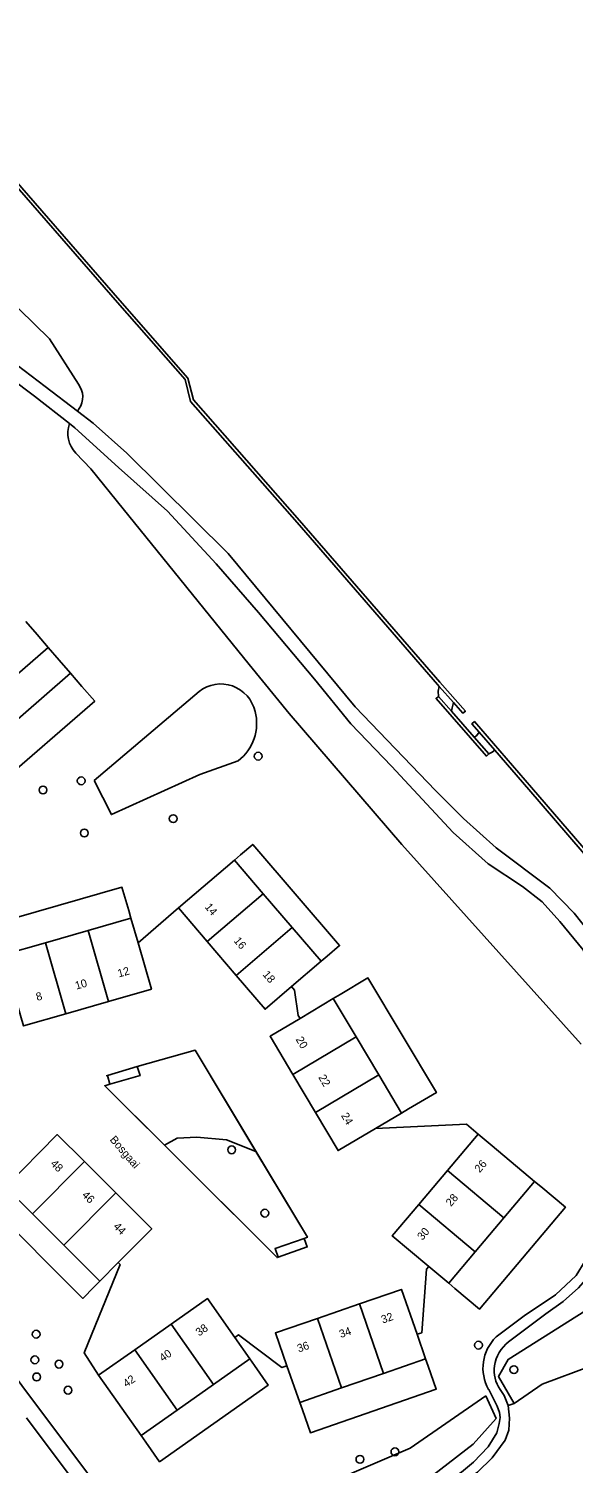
# Model space of a CAD drawing. Extents: x 156664 to 157568, y 383571 to 384421.
# Drawn here: x 156972.4 to 157040.6, y 384130.7 to 384310 of the extents above; entities that cross this region are included whole.
import ezdxf

# ---------------------------------------------------------------- set-up
doc = ezdxf.new("R2010")
doc.units = 0
for name, color, linetype in [('IMGEO_Boom', 7, 'Continuous'), ('IMGEO_Grasland_overig', 7, 'Continuous'), ('IMGEO_Greppel_droge_sloot', 7, 'Continuous'), ('IMGEO_Groenvoorziening', 7, 'Continuous'), ('IMGEO_Hek', 7, 'Continuous'), ('IMGEO_Houtwal', 7, 'Continuous'), ('IMGEO_Kademuur', 7, 'Continuous'), ('IMGEO_Loofbos', 7, 'Continuous'), ('IMGEO_Meer_plas_ven_vijver', 7, 'Continuous'), ('IMGEO_Muur', 7, 'Continuous'), ('IMGEO_Openbare_ruimte_label', 7, 'Continuous'), ('IMGEO_Pand', 7, 'Continuous'), ('IMGEO_Pand_nummerreeks', 7, 'Continuous'), ('IMGEO_Voetpad_halfverhard', 7, 'Continuous'), ('IMGEO_Voetpad_open', 7, 'Continuous'), ('IMGEO_Waterloop', 7, 'Continuous')]:
    doc.layers.add(name, color=color, linetype=linetype)

msp = doc.modelspace()

# ---------------------------------------------------------------- linework, layer by layer
at = {"layer": 'IMGEO_Boom'}
for centre in [(157001.12, 384219.07), (156978.98, 384215.99), (156974.2, 384214.85), (156990.49, 384211.27), (156979.37, 384209.47), (156997.8, 384169.88), (157001.96, 384161.96), (156973.34, 384146.83), (157028.68, 384145.46), (156973.18, 384143.62), (156976.2, 384143.09), (157033.11, 384142.4), (156973.41, 384141.49), (156977.33, 384139.83), (157018.23, 384132.13), (157013.85, 384131.19)]:
    msp.add_circle(centre, 0.489, dxfattribs=at)
at = {"layer": 'IMGEO_Grasland_overig'}
for points in [[(156986, 384180.27), (156993.22, 384182.35), (157000.84, 384169.66)], [(156982.58, 384178.07), (156982.26, 384179.17), (156986, 384180.27)], [(156986, 384180.27), (156986.35, 384179.16), (156982.58, 384178.07)], [(156989.38, 384170.45), (156981.92, 384177.88), (156982.58, 384178.07)], [(156989.38, 384170.45), (156990.98, 384171.33), (156993.45, 384171.47), (156997.15, 384171.11), (157000.84, 384169.66)], [(157003.64, 384156.45), (157003.49, 384156.4), (156989.38, 384170.45)], [(157000.84, 384169.66), (157007.28, 384158.95), (157006.89, 384158.81)], [(157003.64, 384156.45), (157003.24, 384157.52), (157006.89, 384158.81)], [(157006.89, 384158.81), (157007.25, 384157.74), (157003.64, 384156.45)]]:
    msp.add_lwpolyline(points, dxfattribs=at)
at = {"layer": 'IMGEO_Greppel_droge_sloot'}
for points in [[(157073.18, 384136.62), (157070.19, 384141.01), (157064.98, 384144.51), (157061.93, 384147.4), (157059.42, 384149.63), (157057.67, 384151.81), (157054.48, 384157.38), (157052.61, 384158.91), (157049.33, 384158.7), (157048.02, 384157.03), (157047.08, 384153.92), (157045.3, 384151.79), (157032.38, 384143.68), (157031.2, 384141.56), (157033.15, 384138.17)], [(157033.15, 384138.17), (157036.64, 384140.57), (157042.69, 384142.82), (157047.48, 384142.77), (157050.7, 384143.97), (157052.89, 384145.51), (157055.6, 384145.94), (157058.37, 384145.32), (157062.52, 384143.02), (157073.18, 384136.62)], [(157029.6, 384139.14), (157030.88, 384136.29), (157028.03, 384133.07), (157020.85, 384127.54), (157011.12, 384122.68), (157001.81, 384121.29), (156998.76, 384122.64), (157003.7, 384126.69), (157011.98, 384129.07), (157020.14, 384132.57), (157029.6, 384139.14)]]:
    msp.add_lwpolyline(points, dxfattribs=at)
at = {"layer": 'IMGEO_Groenvoorziening'}
for points in [[(156998.14, 384206.08), (156998.9, 384206.73), (157000.44, 384208.05), (157011.3, 384195.41), (157009.75, 384194.09), (157008.99, 384193.45)], [(156969.2, 384194.23), (156968.92, 384195.19), (156968.07, 384198.1), (156984.07, 384202.7), (156984.92, 384199.79), (156985.2, 384198.82)], [(156986.09, 384195.75), (156991.14, 384200.11)], [(157010.52, 384188.78), (157011.39, 384189.29), (157014.84, 384191.35), (157023.41, 384177.02), (157019.93, 384174.98), (157019.06, 384174.47)], [(157005.3, 384190.28), (157005.68, 384189.83), (157006.14, 384186.68), (157006.36, 384186.3)], [(157015.79, 384172.54), (157027.18, 384173.06), (157028.66, 384171.82)], [(157035.7, 384165.92), (157036.48, 384165.27), (157039.56, 384162.69), (157028.83, 384149.97), (157025.73, 384152.55), (157024.96, 384153.19)], [(156981.3, 384153.46), (156980.58, 384152.74), (156979.17, 384151.31), (156967.39, 384163.07)], [(156981.16, 384141.7), (156979.35, 384144.48), (156983.84, 384155.53), (156983.6, 384155.78)], [(157022.46, 384155.29), (157022.19, 384154.96), (157021.59, 384147.02), (157021, 384146.82)], [(157004.72, 384142.89), (157004.1, 384142.68), (156998.67, 384146.73), (156998.21, 384146.41)], [(157000.08, 384143.73), (157000.66, 384142.92), (157002.39, 384140.46), (156988.79, 384130.88), (156987.06, 384133.35), (156986.49, 384134.18)], [(157022.06, 384143.77), (157022.39, 384142.82), (157023.4, 384139.95), (157007.65, 384134.51), (157006.66, 384137.36), (157006.33, 384138.3)], [(157033.15, 384138.17), (157032.41, 384137.9)]]:
    msp.add_lwpolyline(points, dxfattribs=at)
at = {"layer": 'IMGEO_Hek'}
for points in [[(157006.89, 384158.81), (157007.28, 384158.95), (156993.22, 384182.35), (156986, 384180.27)], [(156982.12, 384179.13), (156982.26, 384179.17)], [(156982.26, 384179.17), (156986, 384180.27)], [(156986, 384180.27), (156986.35, 384179.16), (156982.58, 384178.07)], [(156982.58, 384178.07), (156981.92, 384177.88), (157003.49, 384156.4), (157003.64, 384156.45)], [(157003.64, 384156.45), (157003.24, 384157.52), (157006.89, 384158.81)], [(157007.25, 384157.74), (157003.64, 384156.45)]]:
    msp.add_lwpolyline(points, dxfattribs=at)
at = {"layer": 'IMGEO_Houtwal'}
for points in [[(157041.54, 384183.09), (157019.08, 384208.03), (157004.98, 384224.39), (157000, 384230.52), (156984.21, 384250), (156980.17, 384254.98), (156978.29, 384256.96)], [(157023.76, 384227.8), (157023.63, 384227.22), (157023.67, 384226.55)], [(157029.97, 384219.35), (157030.39, 384219.58), (157030.74, 384219.81)]]:
    msp.add_lwpolyline(points, dxfattribs=at)
msp.add_arc((156980.78, 384259.39), 3.48, 158.9292, 224.3425, dxfattribs=at)
at = {"layer": 'IMGEO_Kademuur'}
for points in [[(156926.89, 384340.7), (156925.56, 384342.27), (156926.02, 384342.63), (156939.02, 384327.5), (156962.6, 384300.36), (156983.82, 384276.03), (156992.33, 384266.34), (156993.04, 384263.6), (157006.31, 384248.53), (157023.85, 384228.32), (157027.04, 384224.69), (157026.74, 384224.43), (157025.56, 384225.77)], [(156928.32, 384339.01), (156928.69, 384338.92), (156938.72, 384327.24), (156962.3, 384300.1), (156983.52, 384275.77), (156991.97, 384266.15), (156992.67, 384263.41), (157006.01, 384248.27), (157023.54, 384228.05), (157023.76, 384227.8)], [(157025.56, 384225.77), (157023.76, 384227.8)], [(157023.67, 384226.55), (157023.37, 384226.29), (157029.67, 384219.09), (157029.97, 384219.35)], [(157025.3, 384224.69), (157023.67, 384226.55)], [(157025.3, 384224.69), (157028.13, 384221.45)], [(157028.77, 384222.07), (157027.86, 384223.12), (157028.18, 384223.4), (157035.32, 384215.17), (157047.12, 384201.48), (157062.93, 384183.15), (157070.08, 384174.95), (157082.69, 384160.31), (157085.11, 384157.54), (157084.8, 384157.26), (157083.55, 384158.69)], [(157028.77, 384222.07), (157030.74, 384219.81)], [(157029.97, 384219.35), (157028.13, 384221.45)], [(157030.74, 384219.81), (157035, 384214.9), (157046.8, 384201.21), (157062.62, 384182.87), (157069.77, 384174.67), (157082.37, 384160.03), (157082.75, 384159.6)]]:
    msp.add_lwpolyline(points, dxfattribs=at)
at = {"layer": 'IMGEO_Loofbos'}
for points in [[(156933.49, 384317.37), (156941.08, 384308.28), (156959.02, 384287.93), (156962.79, 384283.9), (156964.73, 384281.22), (156967.39, 384278.64), (156975.02, 384271.25), (156978.62, 384265.56)], [(156978.72, 384262.51), (156978.51, 384262.21)]]:
    msp.add_lwpolyline(points, dxfattribs=at)
msp.add_arc((156976.58, 384263.97), 2.59, 325.6743, 37.9266, dxfattribs=at)
at = {"layer": 'IMGEO_Meer_plas_ven_vijver'}
for points in [[(156980.6, 384216.03), (156993.72, 384227.16)], [(156998.62, 384218.5), (156993.8, 384216.77), (156982.75, 384211.77), (156980.6, 384216.03)]]:
    msp.add_lwpolyline(points, dxfattribs=at)
for centre, radius, start, end in [((156996.44, 384223.71), 4.39, 12.6468, 128.2021), ((156995.06, 384223.16), 5.87, 307.3918, 14.9384)]:
    msp.add_arc(centre, radius, start, end, dxfattribs=at)
at = {"layer": 'IMGEO_Muur'}
for points in [[(156998.9, 384206.73), (157000.44, 384208.05), (157011.3, 384195.41), (157009.75, 384194.09)], [(156998.14, 384206.08), (156998.9, 384206.73)], [(156984.92, 384199.79), (156984.07, 384202.7), (156968.07, 384198.1), (156968.92, 384195.19)], [(156985.2, 384198.82), (156984.92, 384199.79)], [(157008.99, 384193.45), (157009.75, 384194.09)], [(157011.39, 384189.29), (157014.84, 384191.35), (157023.41, 384177.02), (157019.93, 384174.98)], [(157010.52, 384188.78), (157011.39, 384189.29)], [(157019.06, 384174.47), (157019.93, 384174.98)], [(157025.73, 384152.55), (157028.83, 384149.97), (157039.56, 384162.69), (157036.48, 384165.27)], [(157035.7, 384165.92), (157036.48, 384165.27)], [(156980.58, 384152.74), (156979.17, 384151.31), (156967.39, 384163.07)], [(156981.3, 384153.46), (156980.58, 384152.74)], [(157024.96, 384153.19), (157025.73, 384152.55)], [(156987.06, 384133.35), (156988.79, 384130.88), (157002.39, 384140.46), (157000.66, 384142.92)], [(157000.08, 384143.73), (157000.66, 384142.92)], [(157022.39, 384142.82), (157023.4, 384139.95), (157007.65, 384134.51), (157006.66, 384137.36)], [(157022.06, 384143.77), (157022.39, 384142.82)], [(157006.33, 384138.3), (157006.66, 384137.36)], [(156986.49, 384134.18), (156987.06, 384133.35)]]:
    msp.add_lwpolyline(points, dxfattribs=at)
at = {"layer": 'IMGEO_Pand'}
for points in [[(156972.05, 384235.9), (156973.46, 384234.28), (156974.85, 384232.67)], [(156974.85, 384232.67), (156962.63, 384222.08)], [(156974.85, 384232.67), (156976.24, 384231.07), (156977.65, 384229.43)], [(156965.43, 384218.84), (156977.65, 384229.43)], [(156977.65, 384229.43), (156979.07, 384227.8), (156980.67, 384225.95), (156968.44, 384215.36)], [(156991.14, 384200.11), (156998.14, 384206.08)], [(157001.74, 384201.88), (156998.14, 384206.08)], [(156994.75, 384195.9), (157001.74, 384201.88)], [(157005.36, 384197.67), (157001.74, 384201.88)], [(156994.75, 384195.9), (156991.14, 384200.11)], [(156985.2, 384198.82), (156979.86, 384197.29)], [(156985.2, 384198.82), (156986.09, 384195.75)], [(156979.86, 384197.29), (156974.52, 384195.76)], [(156979.86, 384197.29), (156982.4, 384188.42)], [(157005.36, 384197.67), (156998.36, 384191.68)], [(157008.99, 384193.45), (157005.36, 384197.67)], [(156974.52, 384195.76), (156969.2, 384194.23)], [(156977.07, 384186.89), (156974.52, 384195.76)], [(156986.09, 384195.75), (156987.76, 384189.96), (156982.4, 384188.42)], [(156998.36, 384191.68), (156994.75, 384195.9)], [(157008.99, 384193.45), (157005.3, 384190.28)], [(156977.07, 384186.89), (156971.76, 384185.37), (156970.11, 384191.1)], [(157005.3, 384190.28), (157001.99, 384187.44), (156998.36, 384191.68)], [(156982.4, 384188.42), (156977.07, 384186.89)], [(157006.36, 384186.3), (157010.52, 384188.78)], [(157013.37, 384184), (157010.52, 384188.78)], [(157005.45, 384179.3), (157002.61, 384184.07), (157006.36, 384186.3)], [(157005.45, 384179.3), (157013.37, 384184)], [(157016.22, 384179.24), (157013.37, 384184)], [(157008.29, 384174.54), (157005.45, 384179.3)], [(157008.29, 384174.54), (157016.22, 384179.24)], [(157019.06, 384174.47), (157016.22, 384179.24)], [(157015.79, 384172.54), (157011.12, 384169.78), (157008.29, 384174.54)], [(157019.06, 384174.47), (157015.79, 384172.54)], [(156969.51, 384165.2), (156975.99, 384171.77), (156979.37, 384168.4)], [(157024.82, 384167.28), (157028.66, 384171.82)], [(157028.66, 384171.82), (157030.4, 384170.36), (157035.7, 384165.92)], [(156979.37, 384168.4), (156972.87, 384161.86)], [(156979.37, 384168.4), (156983.3, 384164.48)], [(157021.23, 384163.05), (157024.82, 384167.28)], [(157031.86, 384161.37), (157024.82, 384167.28)], [(156969.51, 384165.2), (156972.87, 384161.86)], [(156976.8, 384157.94), (156983.3, 384164.48)], [(156983.3, 384164.48), (156987.8, 384159.99), (156983.6, 384155.78)], [(157031.86, 384161.37), (157035.7, 384165.92)], [(157022.46, 384155.29), (157017.9, 384159.12), (157021.23, 384163.05)], [(157021.23, 384163.05), (157028.28, 384157.12)], [(156972.87, 384161.86), (156976.8, 384157.94)], [(157028.28, 384157.12), (157031.86, 384161.37)], [(156976.8, 384157.94), (156981.3, 384153.46)], [(157024.96, 384153.19), (157028.28, 384157.12)], [(156983.6, 384155.78), (156981.3, 384153.46)], [(157024.96, 384153.19), (157022.46, 384155.29)], [(157013.79, 384150.62), (157019.05, 384152.43), (157021, 384146.82)], [(156990.23, 384148.08), (156994.79, 384151.29), (156998.21, 384146.41)], [(157008.54, 384148.81), (157013.79, 384150.62)], [(157013.79, 384150.62), (157016.78, 384141.93)], [(156985.69, 384144.88), (156990.23, 384148.08)], [(156995.53, 384140.53), (156990.23, 384148.08)], [(157004.72, 384142.89), (157003.28, 384147), (157008.54, 384148.81)], [(157011.54, 384140.11), (157008.54, 384148.81)], [(156998.21, 384146.41), (157000.08, 384143.73)], [(157021, 384146.82), (157022.06, 384143.77)], [(156981.16, 384141.7), (156985.69, 384144.88)], [(156985.69, 384144.88), (156990.99, 384137.34)], [(156995.53, 384140.53), (157000.08, 384143.73)], [(157006.33, 384138.3), (157004.72, 384142.89)], [(157016.78, 384141.93), (157022.06, 384143.77)], [(156986.49, 384134.18), (156981.16, 384141.7)], [(157011.54, 384140.11), (157016.78, 384141.93)], [(156990.99, 384137.34), (156995.53, 384140.53)], [(157006.33, 384138.3), (157011.54, 384140.11)], [(156986.49, 384134.18), (156990.99, 384137.34)]]:
    msp.add_lwpolyline(points, dxfattribs=at)
at = {"layer": 'IMGEO_Voetpad_halfverhard'}
for points in [[(156931.33, 384305.7), (156934.4, 384301.52), (156936.83, 384297.95), (156940.71, 384293.34), (156946.59, 384287.59), (156947.74, 384286.54), (156957.95, 384277.16), (156960.97, 384274.82), (156969.21, 384269.26), (156974.49, 384265.29), (156978.51, 384262.21)], [(156977.53, 384260.64), (156973.15, 384264.09), (156967.17, 384268.51), (156960.61, 384272.78), (156958.35, 384274.47), (156955.36, 384277.02), (156946.46, 384285.34)], [(156978.51, 384262.21), (156980.47, 384260.7), (156984.68, 384256.94), (156997.37, 384244.41), (157013.26, 384225.25), (157023.32, 384214.78), (157026.81, 384211.27), (157030.88, 384207.6), (157037.59, 384202.58), (157040.64, 384199.44), (157043.35, 384196.04), (157046.38, 384190.23), (157047.65, 384186.15), (157047.82, 384185.09), (157048.07, 384183.16)], [(157046.32, 384181.83), (157045.67, 384185.37), (157044.28, 384189.57), (157041.77, 384194.89), (157038.88, 384198.43), (157036.64, 384200.85), (157034.17, 384202.8), (157029.91, 384205.62), (157025.53, 384209.53), (157017.8, 384217.82), (157012.72, 384223.1), (157008.16, 384228.71), (157001.14, 384237.04), (156995.85, 384243.12), (156989.76, 384249.71), (156983.63, 384255.15), (156978.19, 384260.12), (156977.53, 384260.64)], [(157030.9, 384146.49), (157034.38, 384149.12), (157038.31, 384151.74), (157040.89, 384154.15), (157042.01, 384155.98), (157043.22, 384159.6), (157044.19, 384164.08), (157045.6, 384168.56), (157046.91, 384171.94), (157047.33, 384174.35)], [(157032.43, 384145.87), (157037.1, 384149.38), (157039.28, 384150.91), (157041.18, 384152.62), (157042.36, 384153.96), (157043.23, 384155.44), (157043.82, 384157.18), (157044.32, 384159.07), (157045.57, 384164.15), (157046.26, 384166.31), (157047.65, 384170.11), (157047.74, 384170.34), (157047.86, 384170.54)], [(156994.08, 384110.53), (156997.76, 384111.98), (157001.19, 384113.9), (157008.29, 384119.08), (157010.53, 384120.7), (157012.65, 384122.07), (157014.41, 384123.06), (157018.16, 384125.01), (157021.46, 384126.55), (157024.26, 384128.14), (157026.54, 384129.57), (157028.08, 384130.85), (157029.89, 384132.74), (157030.96, 384134.5), (157031.27, 384135.67), (157031.39, 384136.4), (157031.33, 384137.04), (157031.04, 384137.85), (157029.96, 384139.92)], [(157032.41, 384137.9), (157031.89, 384139.17), (157031.39, 384139.9)], [(157032.41, 384137.9), (157032.57, 384136.35), (157032.5, 384134.85), (157032.04, 384133.57), (157030.38, 384131.36), (157028.58, 384129.59), (157026.9, 384128.42), (157025, 384127.19), (157022.01, 384125.53), (157019.08, 384124.07), (157016.07, 384122.57), (157012.99, 384120.72), (157010.01, 384118.79), (157006.92, 384116.53), (157004.4, 384114.6), (157001.44, 384112.45), (156999.47, 384111.24), (156995.24, 384109.03)]]:
    msp.add_lwpolyline(points, dxfattribs=at)
for centre, radius, start, end in [((157034.62, 384142.6), 5.38, 133.7652, 209.9038), ((157035.46, 384142.09), 4.84, 128.6864, 170.7152), ((157034.95, 384142.33), 4.31, 172.705, 214.2296)]:
    msp.add_arc(centre, radius, start, end, dxfattribs=at)
at = {"layer": 'IMGEO_Voetpad_open'}
for points in [[(156960.04, 384155.72), (156983.01, 384125.14), (156990.47, 384115.21), (156994.08, 384110.53)], [(156979.61, 384126.4), (156972.12, 384136.36)]]:
    msp.add_lwpolyline(points, dxfattribs=at)
at = {"layer": 'IMGEO_Waterloop'}
for points in [[(157025.56, 384225.77), (157025.38, 384225.1), (157025.3, 384224.69)], [(157028.13, 384221.45), (157028.43, 384221.62), (157028.77, 384222.07)]]:
    msp.add_lwpolyline(points, dxfattribs=at)

# ---------------------------------------------------------------- texts
at = {"layer": 'IMGEO_Openbare_ruimte_label'}
msp.add_text('Bosgaai', height=1, rotation=310.8624, dxfattribs=at).set_placement((156982.49, 384171.1))
at = {"layer": 'IMGEO_Pand_nummerreeks'}
for s, rotation, p in [('14', 310.6078, (156994.38, 384200.19)), ('16', 310.6078, (156998, 384195.97)), ('10', 16.0012, (156978.37, 384189.89)), ('12', 16.0012, (156983.69, 384191.41)), ('18', 310.6078, (157001.62, 384191.75)), ('8', 16.0012, (156973.48, 384188.48)), ('20', 300.7619, (157005.78, 384183.68)), ('22', 300.7619, (157008.61, 384178.93)), ('24', 300.7619, (157011.45, 384174.16)), ('48', 315.0888, (156975.06, 384168.06)), ('26', 49.7297, (157028.84, 384166.95)), ('46', 315.0888, (156979, 384164.14)), ('28', 49.7297, (157025.25, 384162.72)), ('44', 315.0888, (156982.93, 384160.21)), ('30', 49.7297, (157021.67, 384158.49)), ('38', 35.1176, (156993.73, 384146.53)), ('32', 18.9819, (157016.7, 384148.15)), ('34', 18.9819, (157011.45, 384146.34)), ('40', 35.1176, (156989.19, 384143.34)), ('36', 18.9819, (157006.19, 384144.54)), ('42', 35.1176, (156984.64, 384140.14))]:
    msp.add_text(s, height=1, rotation=rotation, dxfattribs=at).set_placement(p)

doc.saveas('drawing.dxf')
